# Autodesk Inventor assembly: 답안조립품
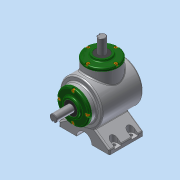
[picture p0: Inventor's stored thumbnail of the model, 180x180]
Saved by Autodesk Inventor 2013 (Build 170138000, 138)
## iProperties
Created: 2017-04
Part Number: 답안조립품
Document SubType Name: Assembly
Designer: dgall
Author: dgall
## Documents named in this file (14)
- C:\Users\dgall\Desktop\470407V1004\답안조립품.iam
- C:\Users\dgall\Desktop\470407V1004\본체.ipt
- C:\Users\dgall\Desktop\470407V1004\커버.ipt
- C:\Users\dgall\Desktop\470407V1004\볼트 M4.ipt
- C:\Users\dgall\Desktop\470407V1004\오일실 17 32 8.ipt
- C:\Users\dgall\Desktop\470407V1004\베어링 6203.ipt
- C:\Users\dgall\Desktop\470407V1004\메인 축.ipt
- 메인 축.ipt
- C:\Users\dgall\Desktop\470407V1004\서브 축.ipt
- 서브 축.ipt
- C:\Users\dgall\Desktop\470407V1004\키 5x5.ipt
- C:\Users\dgall\Desktop\470407V1004\키 4x4.ipt
- C:\Users\dgall\Desktop\470407V1004\메인 베벨기어.ipt
- C:\Users\dgall\Desktop\470407V1004\서브 베벨기어.ipt
